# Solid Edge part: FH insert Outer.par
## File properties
Author: Dan
Template: FH Insert .par
Last saved by: Dan
Revision: 32
Application: Solid Edge
Density: 7833.000 kg/m^3
Accuracy: 0.990
Material: Steel
Face Style: Steel
Fill Style: ANSI32(Steel)
Virtual Style: Machined steel
Coef. of Thermal Exp: 1.3e-05
Thermal Conductivity: 32.0
Specific Heat: 481.0
Modulus of Elasticity: 199947953000.0
Poisson's Ratio: 0.29
Yield Stress: 262000766.0
Ultimate Stress: 358527364.0
Elongation: 0.0
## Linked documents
FH Insert .par
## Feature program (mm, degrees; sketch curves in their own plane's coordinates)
part copy "CopiedPart_1"
sketch for "ExtrudedCutout_1" plane through (0, 0, -36) normal (0, 0, -1) x-axis (-1, 0, 0)
  circle centre (0, 0) radius 22.25
extrude "ExtrudedCutout_1" cut finite 5.03 along -normal
sketch for "Hole_5" plane through (0, 0, -36) normal (0, 0, -1) x-axis (-1, 0, 0)
  hole centre (-39.8448, 16.1322) bore radius 2.4585
hole "Hole_5" finite
sketch for "unnamed Hole 1" plane through (0, 0, -36) normal (0, 0, -1) x-axis (-1, 0, 0)
hole "unnamed Hole 1" finite
sketch for "unnamed Hole 2" plane through (0, 0, -36) normal (0, 0, -1) x-axis (-1, 0, 0)
  hole centre (16.1322, 39.893) bore radius 2.4585
hole "unnamed Hole 2" finite
sketch for "unnamed Hole 3" plane through (0, 0, -36) normal (0, 0, -1) x-axis (-1, 0, 0)
  hole centre (39.893, -16.084) bore radius 2.4585
hole "unnamed Hole 3" finite
pattern "unnamed Pattern 1" of "Hole_5", "unnamed Hole 1", "unnamed Hole 2", "unnamed Hole 3"
sketch for "Hole_9" plane through (0, 0, -36) normal (0, 0, -1) x-axis (-1, 0, 0)
hole "Hole_9" finite
sketch for "unnamed Hole 4" plane through (0, 0, -36) normal (0, 0, -1) x-axis (-1, 0, 0)
hole "unnamed Hole 4" finite
pattern "unnamed Pattern 2" of "Hole_9", "unnamed Hole 4"
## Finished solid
Body 1: solid body, 127 faces, 251 edges, 124 vertices.
  Faces by surface: plane 76, cylinder 25, cone 15, sphere 8, spun 2, torus 1
  Edges by curve: line 166, circle 81, intersection 4
Bounding box of the edges (mm; curved faces can reach further): 116.000 x 116.000 x 26.842, from (-58, -58, -36) to (58, 58, -9.1581).
Cylindrical faces by radius (mm): R2.4585 x4, R3 x2, R18.8116 x1, R21.8198 x1, R22.25 x1, R26.8948 x1, R31.4973 x1, R35.75 x1, R38.57 x2, R38.8542 x2, R40.75 x1, R45.5 x1, R53 x1, R55.65 x2, R58 x4
Conical faces (half-angle, radius in mm at the cone's reference point): 2 deg R19.3388 x1, 3 deg R0.55 x8, 59 deg R2.4585 x4, 59 deg R3 x2
Toroidal faces (ring radius, tube radius in mm): R20.4107 r1.015 x1
Spherical faces by radius (mm): R3 x8
Planar faces by outward normal: +x 14, +y 10, +z 17, -x 10, -y 18, -z 5, oblique 2
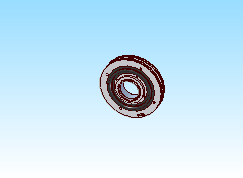
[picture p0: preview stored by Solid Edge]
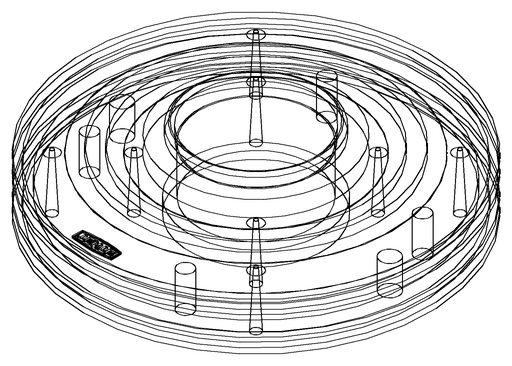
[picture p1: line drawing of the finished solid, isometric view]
